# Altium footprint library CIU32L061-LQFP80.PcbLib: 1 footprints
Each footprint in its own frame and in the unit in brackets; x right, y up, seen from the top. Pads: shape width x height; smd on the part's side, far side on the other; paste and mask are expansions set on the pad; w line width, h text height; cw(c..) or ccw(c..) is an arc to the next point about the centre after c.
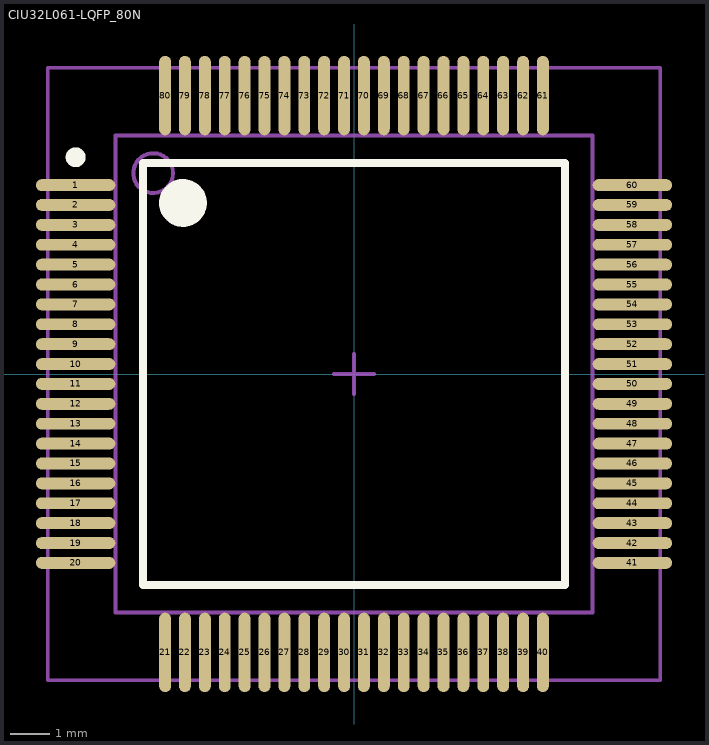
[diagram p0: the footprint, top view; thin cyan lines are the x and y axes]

## CIU32L061-LQFP_80N [mm]
height 1.4
pads (80):
  oval 2x0.3 smd: 1(-7,4.75) 2(-7,4.25) 3(-7,3.75) 4(-7,3.25) 5(-7,2.75) 6(-7,2.25) 7(-7,1.75) 8(-7,1.25) 9(-7,0.75) 10(-7,0.25) 11(-7,-0.25) 12(-7,-0.75) 13(-7,-1.25) 14(-7,-1.75) 15(-7,-2.25) 16(-7,-2.75) 17(-7,-3.25) 18(-7,-3.75) 19(-7,-4.25) 20(-7,-4.75) 41(7,-4.75) 42(7,-4.25) 43(7,-3.75) 44(7,-3.25) 45(7,-2.75) 46(7,-2.25) 47(7,-1.75) 48(7,-1.25) 49(7,-0.75) 50(7,-0.25) 51(7,0.25) 52(7,0.75) 53(7,1.25) 54(7,1.75) 55(7,2.25) 56(7,2.75) 57(7,3.25) 58(7,3.75) 59(7,4.25) 60(7,4.75)
  oval 0.3x2 smd: 21(-4.75,-7) 22(-4.25,-7) 23(-3.75,-7) 24(-3.25,-7) 25(-2.75,-7) 26(-2.25,-7) 27(-1.75,-7) 28(-1.25,-7) 29(-0.75,-7) 30(-0.25,-7) 31(0.25,-7) 32(0.75,-7) 33(1.25,-7) 34(1.75,-7) 35(2.25,-7) 36(2.75,-7) 37(3.25,-7) 38(3.75,-7) 39(4.25,-7) 40(4.75,-7) 61(4.75,7) 62(4.25,7) 63(3.75,7) 64(3.25,7) 65(2.75,7) 66(2.25,7) 67(1.75,7) 68(1.25,7) 69(0.75,7) 70(0.25,7) 71(-0.25,7) 72(-0.75,7) 73(-1.25,7) 74(-1.75,7) 75(-2.25,7) 76(-2.75,7) 77(-3.25,7) 78(-3.75,7) 79(-4.25,7) 80(-4.75,7)
Top Overlay:
  circle w0.6: c-4.3,4.3 r0.3
  circle w0.25: c-7,5.45 r0.125
  lines w0.2: -5.3,-5.3 5.3,-5.3 5.3,5.3 -5.3,5.3 -5.3,-5.3
Mechanical 13:
  circle w0.1: c-5.05,5.05 r0.5
  lines w0.1: -6,-6 6,-6 6,6 -6,6 -6,-6
Mechanical 15:
  lines w0.1: -0.5,0 0.5,0 ; 0,-0.5 0,0.5 ; -7.7,-7.7 7.7,-7.7 7.7,7.7 -7.7,7.7 -7.7,-7.7
3D body: height 1.4, standoff 0.15, extent -6,-6 6,6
